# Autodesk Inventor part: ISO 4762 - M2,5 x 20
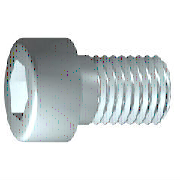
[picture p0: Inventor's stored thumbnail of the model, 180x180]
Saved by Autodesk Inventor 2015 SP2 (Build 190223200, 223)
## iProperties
Created: 2014-02
Part Number: ISO 4762 - M2,5 x 20
Material: Edelstahl, 440C
Description: Innensechskantschraube
Document SubType Name: Modeling
Standard: ISO 4762
Designer: rYan
Standard Revision: Fourth edition 2004-03-01
Standards Organization: ISO
Language: de-DE
Size Designation: M2,5 x 20
Categories: <MemberInstance><Categories><Category DisplayName="Verbindungselemente" InternalName="e4da775c-781d-43d5-af7c-5136215cf5a6" Mnemonic="FSTN"><Category DisplayNam
Density: 7.75 g/cm^3
Appearance: Halbpoliert
IsCustomPart: 0
Author: rYan
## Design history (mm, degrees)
sketch "Skizze1"
  geometry: L1 (-0.733, 0)-(20, 0); L2 (20, 0)-(20, 1.25); L3 (20, 1.25)-(1.125, 1.25); L4 (1.125, 1.25)-(0.849, 1.25); L5 (0.849, 1.25)-(0, 1.25); L6 (0, 1.25)-(0, 2.25); L7 (0, 2.25)-(-2.5, 2.25); L8 (-2.5, 2.25)-(-2.5, 1.155); L9 (-2.5, 1.155)-(-1.4, 1.155); L10 (-1.4, 1.155)-(-0.733, 0); L11 (-7, 0)-(24.5, 0) reference; L12 (0, -0.45)-(0, 2.7) reference; L13 (1.125, 1.25)-(0, 1.25)
  constraints: 22 end point, 6 parallel, 2 collinear, 2 perpendicular, 1 horizontal, 1 point on line
  dimensions: "d1" = 18.875 distance from line of L3.end L2 (= GEL); "d2" = 0.27615 distance of L4.end L3.end (computed from GAL); "d3" = 2.5 distance between parallel lines of L8 L6 (= KOH); "d4" = 1.1 distance of L8.end L9.end (= INTI); "d5" = 60 deg angle of L10 L1; "d6" = 2.5 diameter of L3 L1 (= GD); "d7" = 2.5 diameter of L5 L1 (= BDM); "d8" = 2.3094 diameter of L9 L1 (= 1.1547 x SW); "d9" = 4.5 diameter of L7 L1 (= KOD); "d26" = 20 distance between parallel lines of L12 L2 (= NLG)
revolve "Körper" sketch "Skizze1" stored, may be unused: angle "d10" = 90 deg
sketch "Skizze2"
  geometry: L1 (0, -3.15)-(0, 3.15) reference; L2 (-3.15, 0)-(3.15, 0) reference; L3 (1.155, 0)-(0.577, -1); L4 (0.577, -1)-(-0.577, -1); L5 (-0.577, -1)-(-1.155, 0); L6 (-1.155, 0)-(-0.577, 1); L7 (-0.577, 1)-(0.577, 1); L8 (0.577, 1)-(1.155, 0); 2 further points
  constraints: 12 end point, 1 coincident, 1 horizontal alignment, 1 point on line, 12 other
extrude "Loch" join sketch "Skizze2" stored distance "d11" = 10; taper "d12" = 0 deg
workplane "Work Plane1"
fillet "Fillet2" dims "d30" = 0.1 (= R)
body "Solid1"
fillet "Rundung1" dims "d17" = 0.25 (= RR)
feature "Gewinde" dims "d13" = 18.875 (= GEL), "d14" = 0
chamfer "Fase1" distance "d15" = 0.27605 (= -0.5 x SPD + 0.5 x GD); stored, may be unused: second distance "d16" = 0.27605 (= GUL), angle "d27" = 45 deg
other parameters: "GD" = 2.5 [user parameter; used in 2 equation terms], "NLG" = 20 [user parameter; used in 1 equation term], "GEL" = 18.875 [user parameter; used in 2 equation terms], "KOD" = 4.5 [user parameter; used in 1 equation term], "KOH" = 2.5 [user parameter; used in 1 equation term], "INTI" = 1.1 [user parameter; used in 1 equation term], "GAL" = 0.27605 (= 0.61345 x PTC) [user parameter; used in 1 equation term], "GUL" = 0.27605 (= 0.61345 x PTC) [user parameter; used in 1 equation term], "BDM" = 2.5 (= NND) [user parameter; used in 1 equation term], "SW" = 2 [user parameter; used in 2 equation terms], "RR" = 0.25 [user parameter; used in 1 equation term], "SPD" = 1.94789 (= NND - 1.2269 x PTC) [user parameter; used in 1 equation term], "d19" = 0, "d28" = 0, "d29" = 0, "R" = 0.1 [user parameter; used in 1 equation term], "TOA" = 30 deg [user parameter], "GD1" = 1.94789 (= THREADDIA - 1.2269 x PTC) [user parameter], "THREADDIA" = 2.5 [user parameter; used in 1 equation term], "FAWI" = 45 deg [user parameter], "TPU" = 22.22222 (computed from PTC) [user parameter], "PTC" = 0.45 [user parameter; used in 5 equation terms], "NND" = 2.5 [user parameter; used in 2 equation terms], "E0" = 2.31 (= 1.155 x SW) [user parameter]
